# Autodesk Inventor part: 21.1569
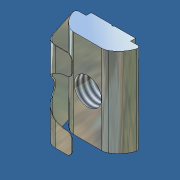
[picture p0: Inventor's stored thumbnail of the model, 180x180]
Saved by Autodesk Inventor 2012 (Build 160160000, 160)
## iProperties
Created: 2012-02
Part Number: 21.1569
Document SubType Name: Modeling
Designer: Administrator
Density: 7.85 g/cm^3
Material: Steel
Mass: 4.86141 g
Surface Area: 8.61152 cm^2
Volume: 0.619288 cm^3
Description: M6 SQUARE NUT 30
Vendor: S
Author: Administrator
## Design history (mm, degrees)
sketch "Sketch1"
  geometry: L1 (-4, 0)-(4, 0); L2 (4, 0)-(4, -0.9); L3 (-4, 0)-(-4, -0.9); L4 (-4, -0.9)-(-5.25, -0.9); L5 (4, -0.9)-(5.25, -0.9); L6 (-2.5, -4.6)-(2.5, -4.6); A1 r 5 centre (-0.966, -0.022) between (-5.726, -1.553) and (-3.522, -4.319); A2 r 5 centre (0.966, -0.022) between (3.522, -4.319) and (5.726, -1.553); A3 r 0.5 centre (5.25, -1.4) between (5.726, -1.553) and (5.25, -0.9); A4 r 0.5 centre (-5.25, -1.4) between (-5.25, -0.9) and (-5.726, -1.553); A5 r 2 centre (-2.5, -2.6) between (-3.522, -4.319) and (-2.5, -4.6); A6 r 2 centre (2.5, -2.6) between (2.5, -4.6) and (3.522, -4.319); 3 further points
  constraints: 12 end point, 12 point on circle, 8 tangent, 6 centre point, 2 equal length, 2 equal radius, 2 midpoint, 2 parallel, 2 perpendicular, 1 coincident, 1 collinear, 1 horizontal, 1 vertical alignment
  dimensions: "d0" = 0.9 distance of L1.end L2.end; "d1" = 8 distance of L1.start L1.end; "d2" = 4.6 distance between parallel lines of L6 L1; "d4" = 5 radius of A1; "d5" = 5 radius of A2 (= d4); "d6" = 0.5 radius of A3; "d7" = 2 radius of A5; "d8" = 11.5 dimension on A3 A4; "d9" = 5 distance of L6.start L6.end
extrude "Extrusion1" new body sketch "Sketch1" stored distance "d10" = 16; taper "d11" = 0 deg
sketch "Sketch2"
  geometry: L1 (-4, 0)-(4, 0) reference; L2 (-0.25, 0)-(0, -0.25); L3 (0, -0.25)-(0.25, 0); 2 further points
  constraints: 4 end point, 2 point on line, 1 midpoint, 1 vertical alignment
  dimensions: "d12" = 45 deg angle of L1 L2; "d13" = 90 deg angle of L3 L2; "d14" = 0.25 distance from line of L2.end L1
extrude "Extrusion2" cut sketch "Sketch2" stored distance "d15" = 16; taper "d16" = 0 deg
fillet "Fillet1" dims "d17" = 0.2
sketch "Sketch3"
  geometry: 2 further points
  constraints: 1 coincident
hole "Hole1" sketch "Sketch3" at (4, 8) diameter "d18" = 4.917; stored, may be unused: countersink angle "d22" = 90 deg, drill point angle "d24" = 118 deg; dims "d19" = 6, "d20" = 4, "d21" = 2, "d23" = 8
sketch "Sketch4"
  geometry: L1 (-5.726, -1.553)-(-4.005, -6.901); L2 (-2.102, -8.288)-(0.898, -8.288); L3 (-4, 0)-(-0.25, 0) reference; L4 (0.898, -8.368)-(-2.102, -8.368); L5 (-4.082, -6.925)-(-5.802, -1.578); L6 (-5.802, -1.578)-(-5.726, -1.553); L7 (0.898, -8.288)-(0.898, -8.368); L8 (-4, -0.9)-(-5.25, -0.9) reference; A1 r 2 centre (-2.102, -6.288) between (-4.005, -6.901) and (-2.102, -8.288); A2 r 2.08 centre (-2.102, -6.288) between (-4.082, -6.925) and (-2.102, -8.368); A3 r 5 centre (-0.966, -0.022) between (-5.726, -1.553) and (-3.522, -4.319) reference; 1 further point
  constraints: 12 end point, 4 point on circle, 3 tangent, 2 centre point, 2 perpendicular, 1 horizontal, 2 other
  dimensions: "d26" = 2 radius of A1; "d27" = 0.08 distance between parallel lines of L5 L1; "d28" = 3 distance of L4.start L4.end; "d35" = 7.468 distance between parallel lines of L4 L8
extrude "Extrusion3" join sketch "Sketch4" stored distance "d29" = 16; taper "d30" = 0 deg
sketch "Sketch5"
  geometry: L1 (5, 0)-(5, -16) reference; L2 (2.5, -12.25)-(15.825, -12.25); L3 (15.825, -12.25)-(15.825, -3.75); L4 (15.825, -3.75)-(2.5, -3.75); C1 r 2.458 at (2.5, -8) reference; A1 r 4.25 centre (2.5, -8) between (2.5, -3.75) and (2.5, -12.25)
  constraints: 6 end point, 2 point on circle, 2 tangent, 1 centre point, 1 coincident, 1 perpendicular, 1 vertical, 1 vertical alignment
  dimensions: "d31" = 8.5 diameter of A1
extrude "Extrusion4" cut sketch "Sketch5" distance "d32" = 16; taper "d33" = 0 deg
fillet "Fillet2" dims "d34" = 1
body "Solid1"
